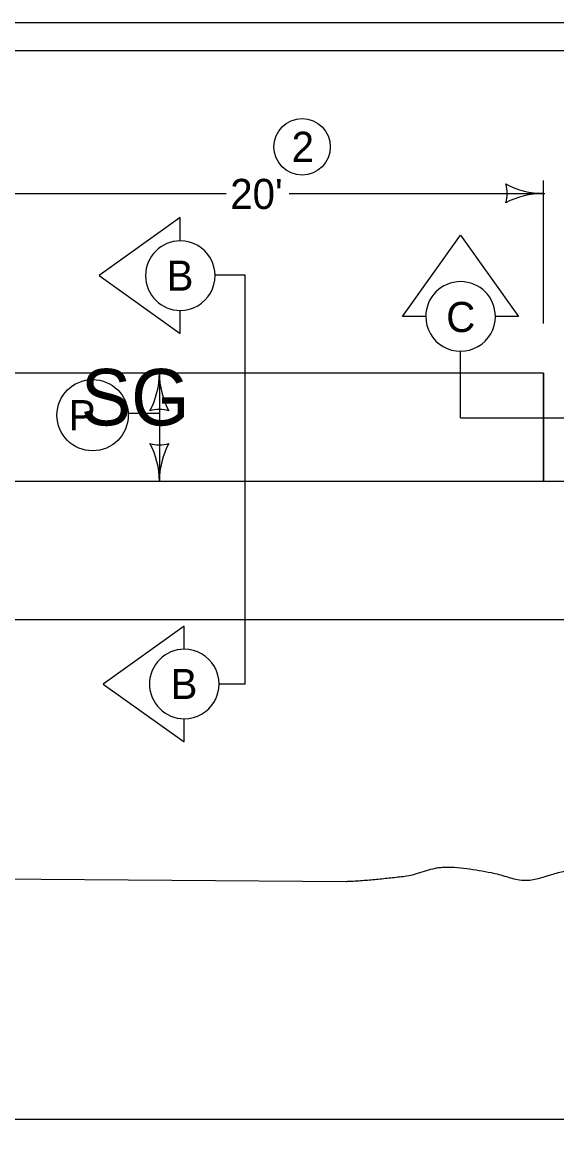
# Model space of a CAD drawing. Extents: x 9538 to 81668, y 7600 to 11751.
# Drawn here: x 29524 to 29808, y 9349 to 9944 of the extents above; entities that cross this region are included whole.
import ezdxf

# ---------------------------------------------------------------- set-up
doc = ezdxf.new("R2010")
doc.units = 0
for name, color, linetype in [('Default', 7, 'Continuous'), ('DsnShtMinorGrid13', 7, 'Continuous'), ('DsnShtMinorGrid16', 7, 'Continuous'), ('dsnStdDimension', 7, 'Continuous'), ('dsnStdNameDate', 7, 'Continuous'), ('dsnStdPattern', 7, 'Continuous'), ('dsnStdShading', 7, 'Continuous'), ('dsnStdTable', 7, 'Continuous')]:
    doc.layers.add(name, color=color, linetype=linetype)

msp = doc.modelspace()

# ---------------------------------------------------------------- linework, layer by layer
at = {"layer": 'Default'}
msp.add_lwpolyline([(28132.56, 9944.02), (31267.56, 9944.02), (31267.56, 7924.02), (28132.56, 7924.02)], close=True, dxfattribs=at)
at = {"layer": 'DsnShtMinorGrid13'}
msp.add_circle((29672.58, 9877.91), 15, dxfattribs=at)
at = {"layer": 'DsnShtMinorGrid16'}
for p, q in [((29800.87, 9757.6), (29496.13, 9757.6)), ((29800.87, 9700.29), (29800.87, 9757.6)), ((28769.18, 9700.29), (29800.87, 9700.29))]:
    msp.add_line(p, q, dxfattribs=at)
msp.add_circle((29561.21, 9735.31), 18.93, dxfattribs=at)
at = {"layer": 'dsnStdDimension'}
for p, q in [((29800.87, 9783.96), (29800.87, 9859.98)), ((29496.13, 9853.15), (29632.13, 9853.15)), ((29665.65, 9853.15), (29801.65, 9853.15)), ((29596.71, 9757.6), (29596.71, 9700.29)), ((29580.14, 9736.43), (29596.71, 9736.43))]:
    msp.add_line(p, q, dxfattribs=at)
msp.add_circle((29561.21, 9735.31), 18.93, dxfattribs=at)
for centre, radius, start, end in [((29765.24, 9853.15), 16.42, 342.26665, 17.73335), ((29800.87, 9895.65), 42.5, 241.92751, 270), ((29800.87, 9810.65), 42.5, 90, 118.07249), ((29554.21, 9757.6), 42.5, 331.92751, 0), ((29639.21, 9757.6), 42.5, 180, 208.07249), ((29596.71, 9721.97), 16.42, 72.26665, 107.73335), ((29596.71, 9735.93), 16.42, 252.26665, 287.73335), ((29554.21, 9700.29), 42.5, 360, 28.07249), ((29639.21, 9700.29), 42.5, 151.92751, 180)]:
    msp.add_arc(centre, radius, start, end, dxfattribs=at)
at = {"layer": 'dsnStdNameDate'}
msp.add_line((30303.14, 9361.02), (28147.56, 9361.02), dxfattribs=at)
at = {"layer": 'dsnStdPattern'}
for p, q in [((29642.38, 9809.76), (29626.61, 9809.76)), ((29642.38, 9592.47), (29642.38, 9809.76)), ((29756.82, 9733.84), (29756.82, 9769.28)), ((29756.82, 9733.84), (29844.92, 9733.84)), ((29642.38, 9592.47), (29628.43, 9592.47))]:
    msp.add_line(p, q, dxfattribs=at)
for points in [[(29607.82, 9827.94), (29607.82, 9840.26), (29564.69, 9809.45), (29607.82, 9778.64), (29607.82, 9790.97)], [(29738.33, 9787.77), (29726.01, 9787.77), (29756.82, 9830.9), (29787.63, 9787.77), (29775.31, 9787.77)], [(29609.94, 9610.96), (29609.94, 9623.28), (29566.81, 9592.47), (29609.94, 9561.66), (29609.94, 9573.99)]]:
    msp.add_lwpolyline(points, dxfattribs=at)
for centre, start, end in [((29607.82, 9809.45), 90.00083, 269.99917), ((29607.82, 9809.45), 269.99917, 90.00083), ((29756.82, 9787.77), 0.00083, 179.99917), ((29756.82, 9787.77), 179.99917, 0.00083), ((29609.94, 9592.47), 90.00083, 269.99917), ((29609.94, 9592.47), 269.99917, 90.00083)]:
    msp.add_arc(centre, 18.49, start, end, dxfattribs=at)
at = {"layer": 'dsnStdShading'}
msp.add_line((28147.56, 9929.02), (31243.25, 9929.02), dxfattribs=at)
at = {"layer": 'dsnStdTable'}
for p, q in [((29735.25, 9787.68), (29726.01, 9787.77)), ((29732.62, 9787.71), (29726.01, 9787.77)), ((29800.87, 9757.6), (29496.13, 9757.6)), ((29800.87, 9757.6), (29800.87, 9700.29)), ((28364.02, 9700.29), (29977.73, 9700.29)), ((28552.03, 9626.66), (29978.03, 9626.66)), ((29366.72, 9490.03), (29695.92, 9487.58))]:
    msp.add_line(p, q, dxfattribs=at)
msp.add_spline([(29695.92, 9487.58), (29697.92, 9487.69), (29705.49, 9488.17), (29713.06, 9488.83), (29720.61, 9489.63), (29728.14, 9490.54), (29732.89, 9491.54), (29737.57, 9492.98), (29742.24, 9494.34), (29744.59, 9494.83), (29746.96, 9495.1), (29753.49, 9495.09), (29760.09, 9494.43), (29766.67, 9493.39), (29773.19, 9492.25), (29777.2, 9491.31), (29781.17, 9490.11), (29785.15, 9488.98), (29789.16, 9488.26), (29792.7, 9488.23), (29796.25, 9488.73), (29803.36, 9490.66), (29810.5, 9492.67), (29817.67, 9493.39), (29832.2, 9492.42), (29846.75, 9491.11), (29853.47, 9490.29), (29860.17, 9489.3), (29866.87, 9488.36), (29873.55, 9487.69), (29879.3, 9488.25), (29884.98, 9490.08), (29890.64, 9492.13), (29896.36, 9493.39), (29903.86, 9493.9), (29911.46, 9494.03), (29922.85, 9493.33), (29926.58, 9492.82), (29933.6, 9491), (29940.49, 9488.43), (29947.41, 9486.06), (29954.52, 9484.83), (29975.63, 9483.83)], degree=3, dxfattribs=at)

# ---------------------------------------------------------------- texts
at = {"layer": 'DsnShtMinorGrid13'}
msp.add_text('2', height=16, dxfattribs=at).set_placement((29667, 9869.91))
at = {"layer": 'dsnStdDimension'}
for s, height, p in [("20'", 16, (29634.37, 9844.87)), ('SG', 30, (29554.92, 9729.87)), ('P', 16, (29548.49, 9727.31))]:
    msp.add_text(s, height=height, dxfattribs=at).set_placement(p)
at = {"layer": 'dsnStdPattern'}
for s, p in [('B', (29600.54, 9801.45)), ('C', (29749.19, 9779.49)), ('B', (29602.64, 9584.47))]:
    msp.add_text(s, height=16, dxfattribs=at).set_placement(p)

doc.saveas('drawing.dxf')
